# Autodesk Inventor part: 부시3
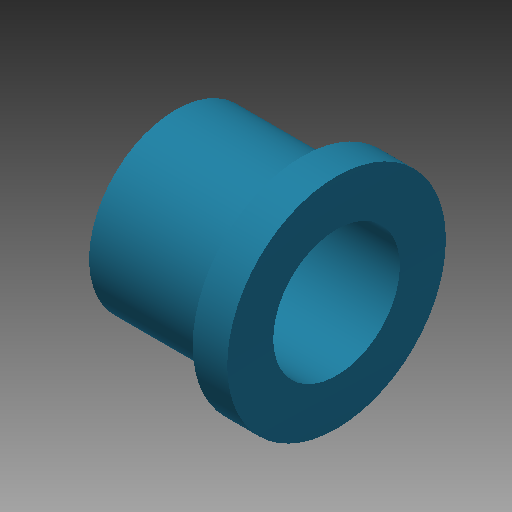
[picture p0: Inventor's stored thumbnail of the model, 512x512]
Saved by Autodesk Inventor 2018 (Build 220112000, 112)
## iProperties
Created: 2020-03
Part Number: 부시3
Material: 스테인리스강
Document SubType Name: Modeling
Designer: mduedu
Density: 8.08 g/cm^3
Appearance: 터키옥색
Mass: 11.829 g
Surface Area: 15.5823 cm^2
Volume: 1.46398 cm^3
Author: mduedu
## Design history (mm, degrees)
sketch "스케치1"
  geometry: L1 (0, 0)-(11, 0); L2 (11, 0)-(11, 7.5); L3 (11, 7.5)-(0, 7.5); L4 (0, 7.5)-(0, 0); L5 (11, 0)-(14, 0); L6 (14, 0)-(14, 9.5); L7 (14, 9.5)-(11, 9.5); L8 (11, 9.5)-(11, 0)
  constraints: 16 end point, 4 parallel, 2 horizontal, 2 perpendicular
  dimensions: "d0" = 14 distance between parallel lines of L6 L4; "d2" = 15 diameter of L3 L1; "d3" = 19 diameter of L7 L5; "d4" = 3 distance of L6.end L7.end
revolve "회전1" sketch "스케치1" stored, may be unused: angle "d5" = 90 deg
hole "구멍1" diameter "d8" = 11; stored, may be unused: countersink angle "d12" = 90 deg, drill point angle "d14" = 118 deg; dims "d9" = 6, "d10" = 4, "d11" = 2, "d13" = 8, "d15" = 10, "d16" = 10
node "솔리드1"
